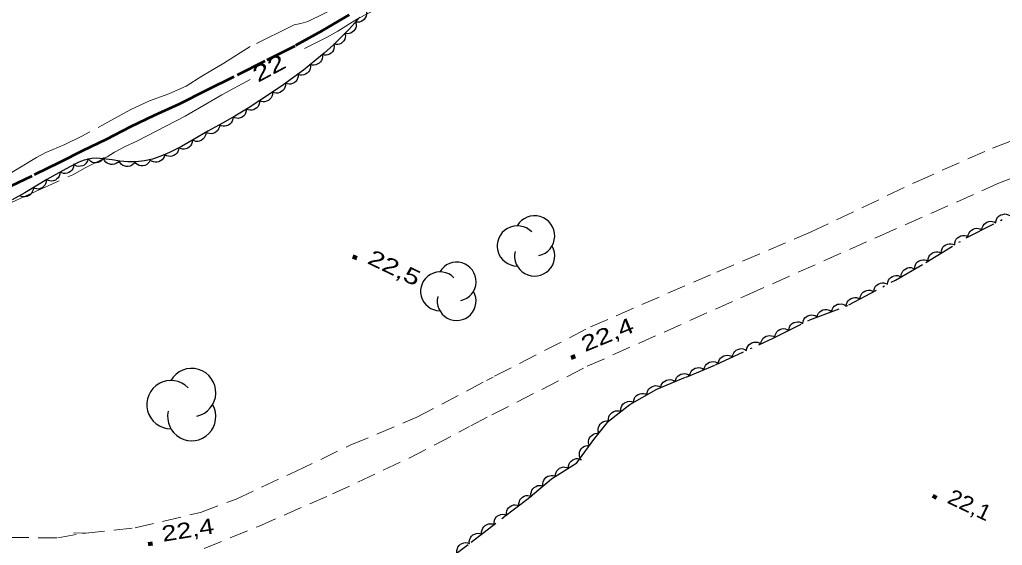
# Model space of a CAD drawing. Extents: x 356765 to 358572, y 5103174 to 5104650.
# Drawn here: x 357017.1 to 357111.7, y 5104205.1 to 5104255.7 of the extents above; entities that cross this region are included whole.
import ezdxf
from ezdxf.enums import TextEntityAlignment as Align

# ---------------------------------------------------------------- set-up
doc = ezdxf.new("R2010")
doc.units = 0
doc.header["$LTSCALE"] = 0.6
for name, pattern in [('DASH_DOUBLE_DOT', [9.2, 5, -1.2, 0.3, -1.2, 0.3, -1.2]), ('DOT_DASHED', [7.7, 5, -1.2, 0.3, -1.2]), ('LONG_DASHED', [7.5, 6, -1.5]), ('MEDIUM_DASHED', [4.5, 3, -1.5])]:
    doc.linetypes.add(name, pattern=pattern)
for name, color, linetype, lineweight in [('19', 7, 'Continuous', 13), ('2', 7, 'Continuous', 13), ('3', 7, 'Continuous', 140), ('4', 7, 'Continuous', 90), ('44', 7, 'Continuous', 25)]:
    doc.layers.add(name, color=color, linetype=linetype, lineweight=lineweight)

msp = doc.modelspace()

# ---------------------------------------------------------------- linework, layer by layer
at = {"layer": '19', "linetype": 'MEDIUM_DASHED'}
for points in [[(357062.86, 5104221.37), (357072.1, 5104226.13), (357084.25, 5104231.41), (357093.35, 5104235.28), (357103.49, 5104240.11), (357110.79, 5104243.35), (357114.53, 5104244.75), (357119.69, 5104246.78), (357122.55, 5104247.84), (357125.75, 5104248.99), (357128.85, 5104250.31), (357134.44, 5104252.39), (357136.51, 5104253.1), (357138.31, 5104253.86), (357140.95, 5104255.24)], [(357060.57, 5104216.59), (357062.61, 5104217.66), (357071.79, 5104222.33), (357087.15, 5104229.19), (357099.91, 5104234.87), (357111.32, 5104239.92), (357122.28, 5104244.24), (357131.17, 5104247.34), (357138.06, 5104249.67), (357143.06, 5104251.7)], [(357022.32, 5104206.29), (357023.19, 5104206.26), (357023.52, 5104206.25), (357028.27, 5104206.79), (357034.55, 5104208.25), (357037.98, 5104209.55), (357043.69, 5104212.21), (357049.04, 5104214.76), (357055.39, 5104217.43), (357062.08, 5104220.96), (357062.73, 5104221.3), (357062.74, 5104221.3)], [(357034.92, 5104204.79), (357040.13, 5104206.91), (357047.26, 5104210.04), (357054.65, 5104213.5), (357060.45, 5104216.53), (357060.46, 5104216.53)], [(356963.6, 5104202.44), (356965.23, 5104203.39), (356966.72, 5104204.31), (356968.85, 5104205.48), (356971.16, 5104206.63), (356972.96, 5104207.39), (356975.75, 5104207.99), (356979.1, 5104208.38), (356982.79, 5104208.67), (356987.75, 5104208.75), (356994.23, 5104207.93), (356997.96, 5104207.22), (357002.58, 5104206.71), (357005.1, 5104206.48), (357009.73, 5104206.15), (357011.41, 5104206), (357016.24, 5104205.85), (357020.83, 5104205.8), (357023.19, 5104206.26)]]:
    msp.add_lwpolyline(points, dxfattribs=at)
at = {"layer": '2'}
for points in [[(357043.18, 5104255.03), (357043.56, 5104255.2), (357044.2, 5104255.33), (357044.89, 5104255.55), (357047.98, 5104257.05), (357049.87, 5104258.18), (357052.24, 5104259.48), (357055.91, 5104261.26), (357057.87, 5104262.34), (357060.02, 5104263.41), (357068.42, 5104268.05), (357071.86, 5104270.01), (357075.34, 5104271.86), (357080.04, 5104274.51), (357085.73, 5104277.58), (357089.17, 5104279.61), (357092.47, 5104281.17), (357093.29, 5104281.63), (357094.86, 5104282.73), (357096.54, 5104284.11), (357098.6, 5104285.67), (357101.23, 5104287.99)], [(357089.1, 5104276.54), (357083.9, 5104273.62), (357080.48, 5104271.93), (357076.96, 5104270.01), (357074.56, 5104268.82), (357073.69, 5104268.33), (357071.67, 5104267.36), (357068.56, 5104265.63), (357062.43, 5104262.49), (357061, 5104261.8), (357060.02, 5104261.46), (357059.28, 5104261.07), (357057.18, 5104259.84), (357054.96, 5104258.69), (357051.86, 5104256.92), (357049.67, 5104255.79), (357047.76, 5104254.59), (357046.74, 5104254.01), (357044.55, 5104252.92)], [(357039.35, 5104249.96), (357036.62, 5104248.47), (357033.07, 5104246.42), (357028.42, 5104244.01), (357027.31, 5104243.49), (357026.29, 5104242.95), (357025.58, 5104242.51)]]:
    msp.add_lwpolyline(points, dxfattribs=at)
at = {"layer": '2', "linetype": 'LONG_DASHED'}
for points in [[(357043.18, 5104255.03), (357039.35, 5104253.12), (357036.79, 5104251.51), (357034.69, 5104250.28), (357033.17, 5104249.3), (357031.51, 5104248.58), (357029.66, 5104247.88), (357027.86, 5104247.07), (357023.14, 5104244.48), (357021.48, 5104243.69), (357019.68, 5104242.91), (357018.77, 5104242.44), (357015.14, 5104240.22)], [(357016.28, 5104238.08), (357017.66, 5104238.73), (357022.25, 5104240.78), (357023.52, 5104241.49), (357025.58, 5104242.51)]]:
    msp.add_lwpolyline(points, dxfattribs=at)
at = {"layer": '3'}
for p, q in [((357049.23, 5104232.9), (357049.59, 5104232.73)), ((357070.24, 5104223.15), (357070.61, 5104223.3)), ((357105.04, 5104209.85), (357105.4, 5104209.68)), ((357029.53, 5104205.2), (357029.92, 5104205.27))]:
    msp.add_line(p, q, dxfattribs=at)
at = {"layer": '4', "linetype": 'DASH_DOUBLE_DOT', "lineweight": 53}
msp.add_lwpolyline([(357015.64, 5104239.39), (357018.58, 5104240.79), (357021.02, 5104241.98), (357023.22, 5104243.11), (357025.5, 5104244.19), (357027.86, 5104245.42), (357030.13, 5104246.51), (357032.53, 5104247.62), (357035.12, 5104248.92), (357038.11, 5104250.4), (357040.98, 5104251.84), (357043.73, 5104253.24), (357046.29, 5104254.66), (357051.69, 5104257.82)], dxfattribs=at)
at = {"layer": '44'}
for points in [[(357050.48, 5104256.62), (357050.53, 5104256.42), (357050.53, 5104256.22), (357050.5, 5104256.05), (357050.42, 5104255.89), (357050.31, 5104255.74), (357050.17, 5104255.62), (357050.03, 5104255.53), (357049.86, 5104255.48), (357049.68, 5104255.46), (357049.5, 5104255.48)], [(357049.49, 5104255.49), (357049.54, 5104255.29), (357049.53, 5104255.08), (357049.5, 5104254.92), (357049.42, 5104254.77), (357049.31, 5104254.62), (357049.16, 5104254.5), (357049.02, 5104254.41), (357048.85, 5104254.37), (357048.67, 5104254.35), (357048.49, 5104254.37)], [(357048.46, 5104254.4), (357048.5, 5104254.2), (357048.48, 5104253.99), (357048.44, 5104253.83), (357048.35, 5104253.68), (357048.23, 5104253.54), (357048.08, 5104253.43), (357047.93, 5104253.35), (357047.76, 5104253.31), (357047.58, 5104253.31), (357047.4, 5104253.34)], [(357047.4, 5104253.34), (357047.43, 5104253.13), (357047.4, 5104252.93), (357047.35, 5104252.77), (357047.25, 5104252.62), (357047.12, 5104252.49), (357046.96, 5104252.39), (357046.82, 5104252.32), (357046.64, 5104252.29), (357046.46, 5104252.3), (357046.28, 5104252.34)], [(357046.28, 5104252.35), (357046.3, 5104252.14), (357046.26, 5104251.94), (357046.2, 5104251.78), (357046.1, 5104251.64), (357045.97, 5104251.51), (357045.8, 5104251.41), (357045.65, 5104251.35), (357045.48, 5104251.33), (357045.29, 5104251.34), (357045.12, 5104251.39)], [(357045.12, 5104251.39), (357045.14, 5104251.18), (357045.1, 5104250.98), (357045.05, 5104250.82), (357044.95, 5104250.68), (357044.81, 5104250.55), (357044.65, 5104250.46), (357044.5, 5104250.39), (357044.32, 5104250.37), (357044.14, 5104250.38), (357043.97, 5104250.43)], [(357043.95, 5104250.45), (357043.96, 5104250.24), (357043.9, 5104250.04), (357043.83, 5104249.89), (357043.72, 5104249.76), (357043.58, 5104249.64), (357043.41, 5104249.56), (357043.25, 5104249.5), (357043.08, 5104249.5), (357042.89, 5104249.52), (357042.72, 5104249.59)], [(357042.72, 5104249.59), (357042.73, 5104249.38), (357042.67, 5104249.18), (357042.6, 5104249.03), (357042.49, 5104248.9), (357042.35, 5104248.78), (357042.18, 5104248.7), (357042.02, 5104248.64), (357041.85, 5104248.64), (357041.66, 5104248.67), (357041.49, 5104248.73)], [(357041.5, 5104248.73), (357041.49, 5104248.52), (357041.43, 5104248.32), (357041.36, 5104248.17), (357041.24, 5104248.04), (357041.09, 5104247.93), (357040.92, 5104247.85), (357040.76, 5104247.81), (357040.59, 5104247.81), (357040.4, 5104247.84), (357040.24, 5104247.91)], [(357038.97, 5104247.1), (357038.96, 5104246.9), (357038.89, 5104246.7), (357038.82, 5104246.56), (357038.7, 5104246.43), (357038.55, 5104246.32), (357038.37, 5104246.25), (357038.21, 5104246.2), (357038.04, 5104246.21), (357037.86, 5104246.25), (357037.69, 5104246.32)], [(357040.24, 5104247.91), (357040.23, 5104247.7), (357040.17, 5104247.51), (357040.1, 5104247.36), (357039.98, 5104247.23), (357039.83, 5104247.12), (357039.65, 5104247.04), (357039.5, 5104246.99), (357039.32, 5104247), (357039.14, 5104247.03), (357038.97, 5104247.1)], [(357037.69, 5104246.33), (357037.67, 5104246.12), (357037.6, 5104245.93), (357037.52, 5104245.78), (357037.39, 5104245.66), (357037.24, 5104245.56), (357037.06, 5104245.49), (357036.9, 5104245.45), (357036.73, 5104245.46), (357036.55, 5104245.5), (357036.39, 5104245.58)], [(357036.38, 5104245.59), (357036.37, 5104245.38), (357036.29, 5104245.19), (357036.21, 5104245.05), (357036.08, 5104244.93), (357035.93, 5104244.82), (357035.74, 5104244.76), (357035.59, 5104244.72), (357035.41, 5104244.74), (357035.23, 5104244.78), (357035.07, 5104244.87)], [(357035.07, 5104244.86), (357035.06, 5104244.65), (357034.98, 5104244.46), (357034.9, 5104244.32), (357034.78, 5104244.19), (357034.63, 5104244.09), (357034.45, 5104244.02), (357034.29, 5104243.98), (357034.11, 5104243.99), (357033.93, 5104244.03), (357033.77, 5104244.11)], [(357032.46, 5104243.38), (357032.44, 5104243.17), (357032.36, 5104242.99), (357032.27, 5104242.85), (357032.14, 5104242.73), (357031.98, 5104242.63), (357031.8, 5104242.57), (357031.64, 5104242.54), (357031.46, 5104242.56), (357031.28, 5104242.61), (357031.13, 5104242.7)], [(357033.77, 5104244.11), (357033.76, 5104243.91), (357033.68, 5104243.72), (357033.6, 5104243.57), (357033.48, 5104243.45), (357033.33, 5104243.34), (357033.15, 5104243.28), (357032.99, 5104243.24), (357032.81, 5104243.25), (357032.63, 5104243.29), (357032.47, 5104243.37)], [(357023.73, 5104242.33), (357023.69, 5104242.13), (357023.59, 5104241.95), (357023.49, 5104241.82), (357023.35, 5104241.71), (357023.18, 5104241.63), (357023, 5104241.59), (357022.83, 5104241.57), (357022.66, 5104241.61), (357022.49, 5104241.67), (357022.34, 5104241.78)], [(357025.24, 5104242.44), (357025.14, 5104242.25), (357024.99, 5104242.11), (357024.86, 5104242.02), (357024.69, 5104241.96), (357024.51, 5104241.93), (357024.32, 5104241.94), (357024.16, 5104241.97), (357024, 5104242.06), (357023.86, 5104242.17), (357023.75, 5104242.31)], [(357031.12, 5104242.71), (357031.07, 5104242.51), (357030.96, 5104242.33), (357030.86, 5104242.2), (357030.71, 5104242.11), (357030.54, 5104242.03), (357030.35, 5104242), (357030.19, 5104241.99), (357030.02, 5104242.03), (357029.85, 5104242.1), (357029.71, 5104242.21)], [(357022.35, 5104241.74), (357022.33, 5104241.54), (357022.25, 5104241.35), (357022.17, 5104241.21), (357022.04, 5104241.09), (357021.89, 5104240.98), (357021.71, 5104240.92), (357021.55, 5104240.89), (357021.37, 5104240.9), (357021.19, 5104240.95), (357021.03, 5104241.03)], [(357026.73, 5104242.12), (357026.59, 5104241.96), (357026.42, 5104241.85), (357026.27, 5104241.78), (357026.09, 5104241.76), (357025.91, 5104241.76), (357025.72, 5104241.82), (357025.57, 5104241.88), (357025.44, 5104242), (357025.32, 5104242.14), (357025.24, 5104242.3)], [(357028.22, 5104241.95), (357028.08, 5104241.79), (357027.92, 5104241.68), (357027.77, 5104241.6), (357027.59, 5104241.57), (357027.41, 5104241.57), (357027.22, 5104241.62), (357027.07, 5104241.68), (357026.93, 5104241.79), (357026.81, 5104241.93), (357026.72, 5104242.09)], [(357029.71, 5104242.18), (357029.61, 5104241.99), (357029.47, 5104241.85), (357029.34, 5104241.74), (357029.18, 5104241.68), (357029, 5104241.64), (357028.81, 5104241.65), (357028.65, 5104241.67), (357028.49, 5104241.75), (357028.34, 5104241.86), (357028.22, 5104241.99)], [(357021.03, 5104241.03), (357021.01, 5104240.82), (357020.94, 5104240.64), (357020.86, 5104240.49), (357020.73, 5104240.37), (357020.58, 5104240.27), (357020.39, 5104240.2), (357020.24, 5104240.17), (357020.06, 5104240.18), (357019.88, 5104240.23), (357019.72, 5104240.31)], [(357018.44, 5104239.52), (357018.43, 5104239.32), (357018.36, 5104239.13), (357018.28, 5104238.98), (357018.16, 5104238.85), (357018.01, 5104238.75), (357017.83, 5104238.68), (357017.67, 5104238.64), (357017.49, 5104238.64), (357017.31, 5104238.68), (357017.15, 5104238.76)], [(357019.72, 5104240.31), (357019.71, 5104240.1), (357019.64, 5104239.91), (357019.57, 5104239.76), (357019.45, 5104239.63), (357019.3, 5104239.52), (357019.12, 5104239.45), (357018.97, 5104239.4), (357018.79, 5104239.41), (357018.61, 5104239.44), (357018.44, 5104239.52)], [(357111.12, 5104236.16), (357111.14, 5104236.36), (357111.23, 5104236.55), (357111.31, 5104236.69), (357111.44, 5104236.81), (357111.6, 5104236.91), (357111.78, 5104236.96), (357111.94, 5104237), (357112.12, 5104236.98), (357112.29, 5104236.93), (357112.45, 5104236.84)], [(357109.78, 5104235.47), (357109.81, 5104235.68), (357109.89, 5104235.87), (357109.98, 5104236.01), (357110.11, 5104236.13), (357110.26, 5104236.22), (357110.45, 5104236.28), (357110.61, 5104236.31), (357110.78, 5104236.29), (357110.96, 5104236.24), (357111.12, 5104236.16)], [(357107.16, 5104234.03), (357107.17, 5104234.23), (357107.24, 5104234.43), (357107.31, 5104234.57), (357107.43, 5104234.7), (357107.58, 5104234.81), (357107.76, 5104234.88), (357107.92, 5104234.92), (357108.09, 5104234.92), (357108.28, 5104234.88), (357108.44, 5104234.8)], [(357108.45, 5104234.79), (357108.47, 5104235), (357108.55, 5104235.18), (357108.64, 5104235.32), (357108.77, 5104235.44), (357108.93, 5104235.54), (357109.11, 5104235.6), (357109.27, 5104235.63), (357109.45, 5104235.61), (357109.62, 5104235.56), (357109.78, 5104235.47)], [(357105.87, 5104233.25), (357105.88, 5104233.46), (357105.95, 5104233.65), (357106.03, 5104233.79), (357106.15, 5104233.92), (357106.3, 5104234.03), (357106.48, 5104234.1), (357106.64, 5104234.14), (357106.81, 5104234.14), (357106.99, 5104234.1), (357107.16, 5104234.03)], [(357104.59, 5104232.47), (357104.6, 5104232.68), (357104.67, 5104232.87), (357104.75, 5104233.02), (357104.87, 5104233.14), (357105.02, 5104233.25), (357105.2, 5104233.32), (357105.35, 5104233.37), (357105.53, 5104233.36), (357105.71, 5104233.32), (357105.87, 5104233.25)], [(357103.3, 5104231.71), (357103.31, 5104231.92), (357103.38, 5104232.11), (357103.46, 5104232.25), (357103.59, 5104232.38), (357103.74, 5104232.48), (357103.92, 5104232.55), (357104.08, 5104232.59), (357104.25, 5104232.58), (357104.43, 5104232.54), (357104.59, 5104232.47)], [(357100.69, 5104230.23), (357100.71, 5104230.44), (357100.79, 5104230.62), (357100.87, 5104230.77), (357101, 5104230.89), (357101.16, 5104230.99), (357101.34, 5104231.05), (357101.5, 5104231.08), (357101.67, 5104231.07), (357101.85, 5104231.02), (357102.01, 5104230.94)], [(357102, 5104230.96), (357102.02, 5104231.16), (357102.09, 5104231.35), (357102.17, 5104231.5), (357102.29, 5104231.62), (357102.44, 5104231.73), (357102.62, 5104231.8), (357102.78, 5104231.84), (357102.96, 5104231.83), (357103.14, 5104231.79), (357103.3, 5104231.71)], [(357099.37, 5104229.52), (357099.39, 5104229.73), (357099.47, 5104229.92), (357099.55, 5104230.06), (357099.68, 5104230.18), (357099.84, 5104230.28), (357100.02, 5104230.34), (357100.18, 5104230.38), (357100.35, 5104230.36), (357100.53, 5104230.31), (357100.69, 5104230.23)], [(357098.04, 5104228.81), (357098.07, 5104229.02), (357098.15, 5104229.21), (357098.23, 5104229.35), (357098.36, 5104229.47), (357098.51, 5104229.57), (357098.69, 5104229.63), (357098.85, 5104229.67), (357099.03, 5104229.65), (357099.21, 5104229.61), (357099.37, 5104229.52)], [(357095.31, 5104227.6), (357095.35, 5104227.8), (357095.46, 5104227.98), (357095.56, 5104228.11), (357095.7, 5104228.21), (357095.87, 5104228.3), (357096.05, 5104228.33), (357096.22, 5104228.35), (357096.39, 5104228.31), (357096.56, 5104228.24), (357096.71, 5104228.14)], [(357096.72, 5104228.11), (357096.74, 5104228.32), (357096.82, 5104228.5), (357096.91, 5104228.64), (357097.03, 5104228.76), (357097.19, 5104228.87), (357097.37, 5104228.93), (357097.53, 5104228.96), (357097.71, 5104228.95), (357097.89, 5104228.9), (357098.04, 5104228.81)], [(357092.54, 5104226.46), (357092.56, 5104226.67), (357092.65, 5104226.85), (357092.74, 5104226.99), (357092.87, 5104227.11), (357093.03, 5104227.2), (357093.21, 5104227.26), (357093.37, 5104227.29), (357093.54, 5104227.27), (357093.72, 5104227.22), (357093.88, 5104227.13)], [(357093.91, 5104227.06), (357093.95, 5104227.27), (357094.06, 5104227.44), (357094.16, 5104227.57), (357094.3, 5104227.68), (357094.46, 5104227.76), (357094.65, 5104227.8), (357094.82, 5104227.81), (357094.99, 5104227.77), (357095.16, 5104227.7), (357095.31, 5104227.6)], [(357091.19, 5104225.79), (357091.22, 5104226), (357091.3, 5104226.19), (357091.39, 5104226.33), (357091.52, 5104226.44), (357091.68, 5104226.54), (357091.87, 5104226.59), (357092.03, 5104226.62), (357092.2, 5104226.6), (357092.38, 5104226.55), (357092.54, 5104226.46)], [(357089.85, 5104225.13), (357089.88, 5104225.33), (357089.96, 5104225.52), (357090.05, 5104225.66), (357090.18, 5104225.78), (357090.34, 5104225.87), (357090.52, 5104225.93), (357090.68, 5104225.96), (357090.86, 5104225.94), (357091.03, 5104225.88), (357091.19, 5104225.79)], [(357087.13, 5104223.86), (357087.16, 5104224.07), (357087.25, 5104224.25), (357087.34, 5104224.39), (357087.48, 5104224.5), (357087.64, 5104224.59), (357087.82, 5104224.64), (357087.98, 5104224.67), (357088.16, 5104224.64), (357088.33, 5104224.59), (357088.49, 5104224.49)], [(357088.49, 5104224.49), (357088.52, 5104224.7), (357088.61, 5104224.88), (357088.7, 5104225.02), (357088.84, 5104225.13), (357089, 5104225.22), (357089.18, 5104225.27), (357089.34, 5104225.3), (357089.52, 5104225.27), (357089.7, 5104225.22), (357089.85, 5104225.12)], [(357084.4, 5104222.6), (357084.44, 5104222.81), (357084.53, 5104222.99), (357084.62, 5104223.13), (357084.76, 5104223.24), (357084.92, 5104223.33), (357085.1, 5104223.38), (357085.26, 5104223.41), (357085.44, 5104223.38), (357085.61, 5104223.33), (357085.77, 5104223.23)], [(357085.77, 5104223.23), (357085.8, 5104223.44), (357085.89, 5104223.62), (357085.98, 5104223.76), (357086.12, 5104223.87), (357086.28, 5104223.96), (357086.46, 5104224.01), (357086.62, 5104224.04), (357086.8, 5104224.01), (357086.97, 5104223.96), (357087.13, 5104223.86)], [(357083.02, 5104222.02), (357083.07, 5104222.22), (357083.16, 5104222.4), (357083.26, 5104222.53), (357083.4, 5104222.64), (357083.56, 5104222.72), (357083.75, 5104222.77), (357083.91, 5104222.79), (357084.09, 5104222.75), (357084.26, 5104222.69), (357084.41, 5104222.59)], [(357080.25, 5104220.87), (357080.3, 5104221.07), (357080.39, 5104221.25), (357080.49, 5104221.38), (357080.63, 5104221.49), (357080.79, 5104221.57), (357080.98, 5104221.62), (357081.14, 5104221.64), (357081.31, 5104221.6), (357081.49, 5104221.54), (357081.64, 5104221.44)], [(357081.64, 5104221.44), (357081.68, 5104221.65), (357081.78, 5104221.82), (357081.88, 5104221.96), (357082.01, 5104222.06), (357082.18, 5104222.15), (357082.37, 5104222.19), (357082.53, 5104222.21), (357082.7, 5104222.18), (357082.87, 5104222.11), (357083.02, 5104222.02)], [(357078.87, 5104220.29), (357078.91, 5104220.5), (357079.01, 5104220.67), (357079.1, 5104220.81), (357079.24, 5104220.91), (357079.41, 5104221), (357079.59, 5104221.04), (357079.76, 5104221.06), (357079.93, 5104221.03), (357080.1, 5104220.96), (357080.25, 5104220.87)], [(357076.24, 5104218.85), (357076.26, 5104219.06), (357076.33, 5104219.25), (357076.41, 5104219.39), (357076.54, 5104219.51), (357076.69, 5104219.62), (357076.87, 5104219.69), (357077.03, 5104219.72), (357077.2, 5104219.71), (357077.38, 5104219.67), (357077.54, 5104219.59)], [(357077.54, 5104219.59), (357077.56, 5104219.8), (357077.63, 5104219.99), (357077.71, 5104220.14), (357077.84, 5104220.26), (357077.99, 5104220.36), (357078.17, 5104220.43), (357078.33, 5104220.47), (357078.5, 5104220.46), (357078.68, 5104220.42), (357078.84, 5104220.34)], [(357075.02, 5104217.98), (357075.01, 5104218.19), (357075.06, 5104218.38), (357075.12, 5104218.54), (357075.22, 5104218.68), (357075.36, 5104218.8), (357075.53, 5104218.89), (357075.68, 5104218.95), (357075.85, 5104218.97), (357076.04, 5104218.95), (357076.21, 5104218.89)], [(357073.84, 5104217.06), (357073.82, 5104217.27), (357073.87, 5104217.47), (357073.93, 5104217.62), (357074.04, 5104217.76), (357074.17, 5104217.89), (357074.34, 5104217.98), (357074.49, 5104218.04), (357074.67, 5104218.05), (357074.85, 5104218.03), (357075.02, 5104217.98)], [(357072.91, 5104215.88), (357072.84, 5104216.08), (357072.84, 5104216.28), (357072.86, 5104216.45), (357072.93, 5104216.61), (357073.03, 5104216.77), (357073.17, 5104216.89), (357073.3, 5104216.99), (357073.47, 5104217.05), (357073.65, 5104217.08), (357073.83, 5104217.07)], [(357071.99, 5104214.7), (357071.92, 5104214.9), (357071.92, 5104215.1), (357071.94, 5104215.27), (357072.01, 5104215.43), (357072.11, 5104215.58), (357072.25, 5104215.71), (357072.38, 5104215.81), (357072.55, 5104215.87), (357072.73, 5104215.89), (357072.91, 5104215.88)], [(357071.11, 5104213.48), (357071.04, 5104213.68), (357071.03, 5104213.88), (357071.05, 5104214.05), (357071.11, 5104214.21), (357071.21, 5104214.37), (357071.34, 5104214.5), (357071.47, 5104214.6), (357071.64, 5104214.66), (357071.82, 5104214.7), (357072, 5104214.69)], [(357069.98, 5104212.53), (357069.98, 5104212.74), (357070.05, 5104212.93), (357070.12, 5104213.08), (357070.24, 5104213.21), (357070.39, 5104213.32), (357070.56, 5104213.4), (357070.72, 5104213.45), (357070.89, 5104213.44), (357071.08, 5104213.41), (357071.24, 5104213.34)], [(357068.72, 5104211.72), (357068.72, 5104211.93), (357068.79, 5104212.12), (357068.86, 5104212.27), (357068.98, 5104212.4), (357069.12, 5104212.51), (357069.3, 5104212.59), (357069.46, 5104212.64), (357069.63, 5104212.63), (357069.81, 5104212.6), (357069.98, 5104212.53)], [(357067.54, 5104210.8), (357067.51, 5104211.01), (357067.55, 5104211.21), (357067.6, 5104211.36), (357067.7, 5104211.51), (357067.83, 5104211.64), (357068, 5104211.74), (357068.15, 5104211.8), (357068.32, 5104211.83), (357068.51, 5104211.82), (357068.68, 5104211.77)], [(357066.39, 5104209.83), (357066.37, 5104210.04), (357066.41, 5104210.24), (357066.46, 5104210.39), (357066.56, 5104210.54), (357066.69, 5104210.67), (357066.86, 5104210.77), (357067, 5104210.84), (357067.18, 5104210.86), (357067.36, 5104210.85), (357067.54, 5104210.8)], [(357065.21, 5104208.91), (357065.2, 5104209.12), (357065.25, 5104209.32), (357065.31, 5104209.47), (357065.42, 5104209.61), (357065.55, 5104209.73), (357065.72, 5104209.82), (357065.88, 5104209.88), (357066.05, 5104209.89), (357066.24, 5104209.87), (357066.41, 5104209.81)], [(357064.01, 5104208.01), (357064, 5104208.22), (357064.05, 5104208.41), (357064.11, 5104208.57), (357064.22, 5104208.71), (357064.36, 5104208.83), (357064.53, 5104208.92), (357064.68, 5104208.98), (357064.85, 5104208.99), (357065.04, 5104208.97), (357065.21, 5104208.91)], [(357062.82, 5104207.1), (357062.81, 5104207.3), (357062.85, 5104207.5), (357062.91, 5104207.66), (357063.02, 5104207.8), (357063.16, 5104207.92), (357063.32, 5104208.01), (357063.48, 5104208.07), (357063.65, 5104208.08), (357063.84, 5104208.07), (357064.01, 5104208.01)], [(357061.63, 5104206.18), (357061.62, 5104206.39), (357061.67, 5104206.59), (357061.72, 5104206.74), (357061.83, 5104206.88), (357061.97, 5104207), (357062.14, 5104207.09), (357062.29, 5104207.16), (357062.46, 5104207.17), (357062.65, 5104207.15), (357062.82, 5104207.1)], [(357060.44, 5104205.26), (357060.43, 5104205.47), (357060.48, 5104205.67), (357060.54, 5104205.82), (357060.64, 5104205.96), (357060.78, 5104206.09), (357060.95, 5104206.18), (357061.1, 5104206.24), (357061.28, 5104206.25), (357061.46, 5104206.24), (357061.63, 5104206.18)], [(357059.24, 5104204.37), (357059.23, 5104204.58), (357059.28, 5104204.78), (357059.34, 5104204.93), (357059.45, 5104205.07), (357059.59, 5104205.19), (357059.76, 5104205.28), (357059.91, 5104205.34), (357060.09, 5104205.35), (357060.27, 5104205.33), (357060.44, 5104205.27)]]:
    msp.add_lwpolyline(points, dxfattribs=at)
at = {"layer": '44', "linetype": 'DOT_DASHED'}
for points in [[(357049.9, 5104255.95), (357048.9, 5104254.83), (357048.26, 5104254.2), (357047.36, 5104253.3), (357046.45, 5104252.49), (357045.57, 5104251.76), (357044.46, 5104250.84), (357043.54, 5104250.16), (357042.57, 5104249.48), (357041.38, 5104248.65), (357040.27, 5104247.93), (357039.13, 5104247.2), (357037.87, 5104246.43), (357036.66, 5104245.74), (357035.26, 5104244.97), (357033.94, 5104244.21), (357032.72, 5104243.51), (357031.56, 5104242.92), (357030.73, 5104242.57), (357029.93, 5104242.29), (357029.15, 5104242.11), (357028.35, 5104242.01), (357027.56, 5104242.01), (357026.78, 5104242.08), (357026.04, 5104242.2), (357024.57, 5104242.38), (357024.09, 5104242.34), (357023.35, 5104242.18), (357022.85, 5104241.98), (357022.05, 5104241.58), (357020.92, 5104240.97), (357019.76, 5104240.33), (357018.87, 5104239.78), (357017.64, 5104239.05), (357016.41, 5104238.36)], [(357108.25, 5104234.69), (357112.1, 5104236.66)], [(357057.92, 5104203.39), (357060.62, 5104205.4), (357063.72, 5104207.79), (357066.11, 5104209.59), (357068.34, 5104211.48), (357070.79, 5104213.05), (357072.43, 5104215.27), (357073.82, 5104217.05), (357075.88, 5104218.64), (357078.48, 5104220.13), (357081.3, 5104221.3), (357084.12, 5104222.47), (357089.69, 5104225.05), (357093.22, 5104226.8), (357096.97, 5104228.24), (357101.46, 5104230.64), (357104.38, 5104232.34), (357108.25, 5104234.69)]]:
    msp.add_lwpolyline(points, dxfattribs=at)
at = {"layer": '44'}
for centre, radius, start, end in [((357066.7181, 5104234.8913), 1.9348, 282.26917, 149.72626), ((357065.0542, 5104233.9239), 1.9348, 44.11537, 269.80396), ((357066.7181, 5104232.9565), 1.9348, 166.93686, 29.62122), ((357059.2113, 5104230.4878), 1.8707, 282.26917, 149.72626), ((357057.6025, 5104229.5525), 1.8707, 44.11537, 269.80396), ((357059.2113, 5104228.6171), 1.8707, 166.93686, 29.62122), ((357033.7104, 5104219.8044), 2.3234, 282.26917, 149.72626), ((357031.7123, 5104218.6428), 2.3234, 44.11537, 269.80396), ((357033.7104, 5104217.4811), 2.3234, 166.93686, 29.62122)]:
    msp.add_arc(centre, radius, start, end, dxfattribs=at)

# ---------------------------------------------------------------- texts
at = {"layer": '2', "width": 1.45}
msp.add_text('22', height=1.5, rotation=28.151, dxfattribs=at).set_placement((357041.5061, 5104250.3885), align=Align.CENTER)
at = {"layer": '3'}
for s, rotation, width, p in [('22,5   ', 334.423, 1.35, (357050.52, 5104232.28)), ('22,4   ', 22.347, 1.35, (357071.57, 5104223.69)), ('22,1   ', 334.619, 1.1, (357106.34, 5104209.22)), ('22,4   ', 9.316, 1.3, (357030.95, 5104205.43))]:
    msp.add_text(s, height=1.5, rotation=rotation, dxfattribs=dict(at, width=width)).set_placement(p)

doc.saveas('drawing.dxf')
